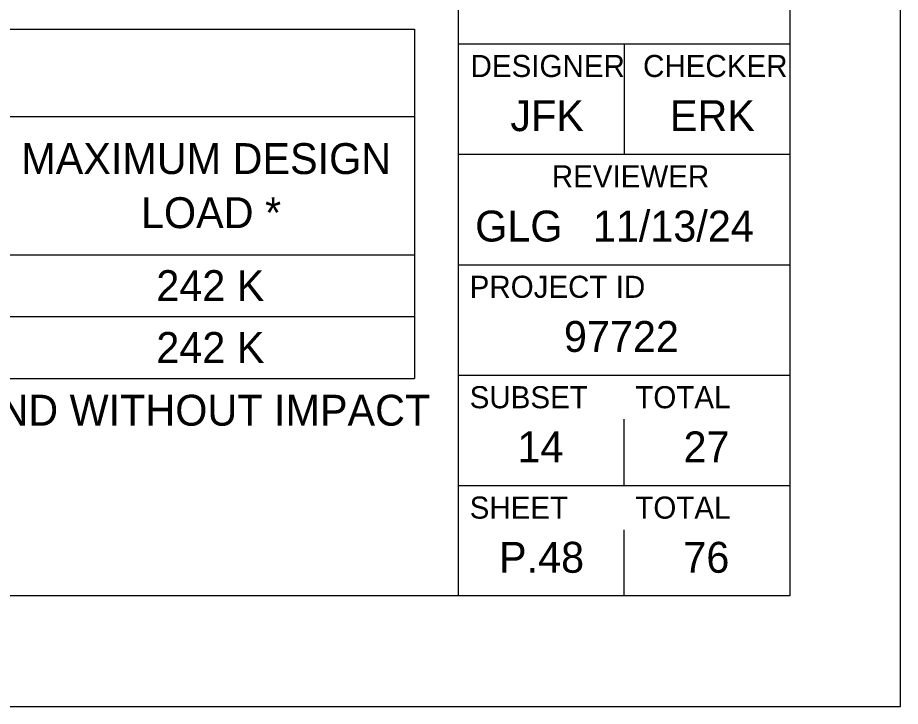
# Model space of a CAD drawing. Extents: x 0 to 34, y 0 to 22.
# Drawn here: x 30.003 to 34, y 0 to 3.119 of the extents above; entities that cross this region are included whole.
import ezdxf

# ---------------------------------------------------------------- set-up
doc = ezdxf.new("R2010")
doc.units = 0
for name, color, linetype in [('SH_Border', 7, 'Continuous'), ('SH_Cut_Line', 7, 'Continuous'), ('SH_Data', 7, 'Continuous'), ('SH_Text', 7, 'Continuous')]:
    doc.layers.add(name, color=color, linetype=linetype)

msp = doc.modelspace()

# ---------------------------------------------------------------- linework, layer by layer
at = {"layer": 'SH_Border'}
for p, q in [((32, 0.5), (32, 21.5)), ((32, 3), (33.5, 3)), ((32.75, 3), (32.75, 2.5)), ((32, 2.5), (33.5, 2.5)), ((32, 2), (33.5, 2)), ((32, 1.5), (33.5, 1.5)), ((32, 1), (33.5, 1))]:
    msp.add_line(p, q, dxfattribs=at)
msp.add_lwpolyline([(1.5, 21.5), (33.5, 21.5), (33.5, 0.5), (1.5, 0.5)], close=True, dxfattribs=at)
at = {"layer": 'SH_Cut_Line'}
msp.add_lwpolyline([(0, 0), (34, 0), (34, 22), (0, 22)], close=True, dxfattribs=at)
at = {"layer": 'SH_Data'}
for p, q in [((32.75, 1), (32.75, 1.3)), ((32.75, 0.5), (32.75, 0.8)), ((32.375, 0.675), (32.375, 0.675))]:
    msp.add_line(p, q, dxfattribs=at)
at = {"layer": 'SH_Text'}
for p, q in [((15.7908, 3.0663), (31.7999, 3.0663)), ((31.7999, 3.0663), (31.7999, 1.4852)), ((15.7908, 2.6711), (31.7999, 2.6711)), ((15.7908, 2.0452), (31.7999, 2.0452)), ((15.7908, 1.7652), (31.7999, 1.7652)), ((15.7908, 1.4852), (31.7999, 1.4852))]:
    msp.add_line(p, q, dxfattribs=at)

# ---------------------------------------------------------------- texts
at = {"layer": 'SH_Data'}
for s, height, p in [('DESIGNER', 0.1, (32.054, 2.85)), ('CHECKER', 0.1, (32.8352, 2.85)), ('JFK', 0.14, (32.2344, 2.605)), ('ERK', 0.14, (32.9565, 2.605)), ('REVIEWER', 0.1, (32.4218, 2.35)), ('GLG', 0.14, (32.075, 2.105)), ('11/13/24', 0.14, (32.6078, 2.105)), ('PROJECT ID', 0.1, (32.05, 1.85)), ('97722', 0.14, (32.4768, 1.605)), ('SUBSET', 0.1, (32.05, 1.35)), ('TOTAL', 0.1, (32.8, 1.35)), ('14', 0.14, (32.2664, 1.105)), ('27', 0.14, (33.0183, 1.105)), ('SHEET', 0.1, (32.05, 0.85)), ('TOTAL', 0.1, (32.8, 0.85)), ('P.48', 0.14, (32.1829, 0.605)), ('76', 0.14, (33.0176, 0.605))]:
    msp.add_text(s, height=height, dxfattribs=at).set_placement(p)
at = {"layer": 'SH_Text'}
for s, p in [('MAXIMUM DESIGN ', (30.0198, 2.4106)), ('LOAD *', (30.5618, 2.1656)), ('242 K', (30.6313, 1.8352)), ('242 K', (30.6313, 1.5552)), ('* REACTIONS ARE UNFACTORED AND WITHOUT IMPACT', (26.7333, 1.2711))]:
    msp.add_text(s, height=0.14, dxfattribs=at).set_placement(p)

doc.saveas('drawing.dxf')
